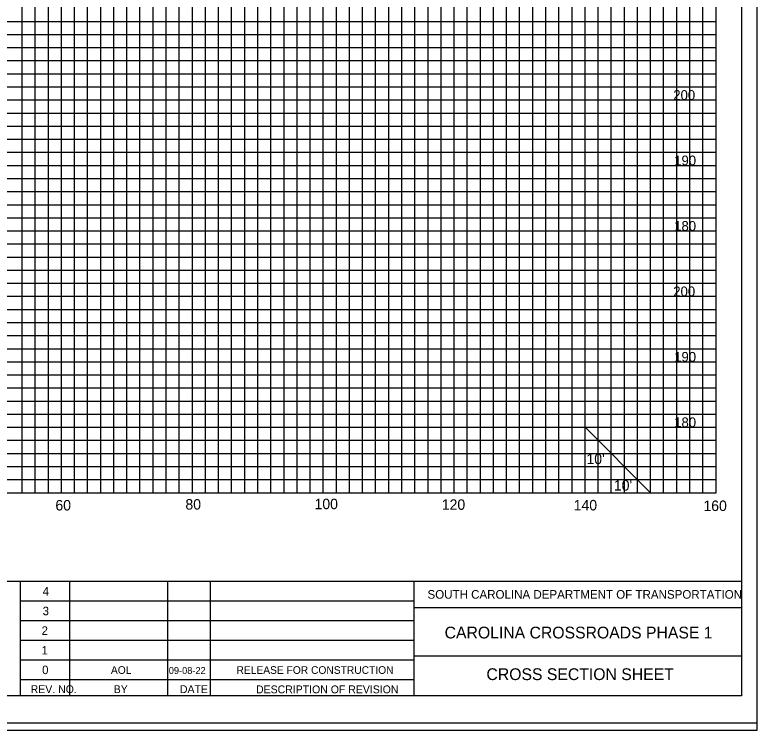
# Model space of a CAD drawing. Extents: x 967 to 1326, y 964 to 2584.
# Drawn here: x 1212.9 to 1326.3, y 2083.7 to 2193 of the extents above; entities that cross this region are included whole.
import ezdxf

# ---------------------------------------------------------------- set-up
doc = ezdxf.new("R2010")
doc.units = 0
for name, color, linetype in [('Default', 7, 'Continuous'), ('RD_GPK_XS_Cell', 7, 'Continuous'), ('RD_SHT_Misc1', 7, 'Continuous'), ('RD_XS_ExGround', 7, 'Continuous'), ('RD_XS_ExPaveRet', 7, 'Continuous'), ('RD_XS_Misc_Line', 7, 'Continuous'), ('RD_XS_TX_Elev_EX', 7, 'Continuous')]:
    doc.layers.add(name, color=color, linetype=linetype)

msp = doc.modelspace()

# ---------------------------------------------------------------- linework, layer by layer
at = {"layer": 'RD_GPK_XS_Cell'}
for p, q in [((1220, 2120), (1220, 2290)), ((1230, 2120), (1230, 2290)), ((1240, 2120), (1240, 2290)), ((1250, 2120), (1250, 2290)), ((1260, 2120), (1260, 2290)), ((1270, 2120), (1270, 2290)), ((1280, 2120), (1280, 2290)), ((1290, 2120), (1290, 2290)), ((1300, 2120), (1300, 2290)), ((1310, 2120), (1310, 2290)), ((1320, 2120), (1320, 2290)), ((1000, 2190), (1320, 2190)), ((1000, 2180), (1320, 2180)), ((1000, 2170), (1320, 2170)), ((1000, 2160), (1320, 2160)), ((1000, 2150), (1320, 2150)), ((1000, 2140), (1320, 2140)), ((1000, 2130), (1320, 2130)), ((1000, 2120), (1320, 2120))]:
    msp.add_line(p, q, dxfattribs=at)
at = {"layer": 'RD_XS_ExGround'}
for p, q in [((1214, 2120), (1214, 2290)), ((1216, 2120), (1216, 2290)), ((1218, 2120), (1218, 2290)), ((1222, 2120), (1222, 2290)), ((1224, 2120), (1224, 2290)), ((1226, 2120), (1226, 2290)), ((1228, 2120), (1228, 2290)), ((1232, 2120), (1232, 2290)), ((1234, 2120), (1234, 2290)), ((1236, 2120), (1236, 2290)), ((1238, 2120), (1238, 2290)), ((1242, 2120), (1242, 2290)), ((1244, 2120), (1244, 2290)), ((1246, 2120), (1246, 2290)), ((1248, 2120), (1248, 2290)), ((1252, 2120), (1252, 2290)), ((1254, 2120), (1254, 2290)), ((1256, 2120), (1256, 2290)), ((1258, 2120), (1258, 2290)), ((1262, 2120), (1262, 2290)), ((1264, 2120), (1264, 2290)), ((1266, 2120), (1266, 2290)), ((1268, 2120), (1268, 2290)), ((1272, 2120), (1272, 2290)), ((1274, 2120), (1274, 2290)), ((1276, 2120), (1276, 2290)), ((1278, 2120), (1278, 2290)), ((1282, 2120), (1282, 2290)), ((1284, 2120), (1284, 2290)), ((1286, 2120), (1286, 2290)), ((1288, 2120), (1288, 2290)), ((1292, 2120), (1292, 2290)), ((1294, 2120), (1294, 2290)), ((1296, 2120), (1296, 2290)), ((1298, 2120), (1298, 2290)), ((1302, 2120), (1302, 2290)), ((1304, 2120), (1304, 2290)), ((1306, 2120), (1306, 2290)), ((1308, 2120), (1308, 2290)), ((1312, 2120), (1312, 2290)), ((1314, 2120), (1314, 2290)), ((1316, 2120), (1316, 2290)), ((1318, 2120), (1318, 2290)), ((1000, 2192), (1320, 2192)), ((1000, 2188), (1320, 2188)), ((1000, 2186), (1320, 2186)), ((1000, 2184), (1320, 2184)), ((1000, 2182), (1320, 2182)), ((1000, 2178), (1320, 2178)), ((1000, 2176), (1320, 2176)), ((1000, 2174), (1320, 2174)), ((1000, 2172), (1320, 2172)), ((1000, 2168), (1320, 2168)), ((1000, 2166), (1320, 2166)), ((1000, 2164), (1320, 2164)), ((1000, 2162), (1320, 2162)), ((1000, 2158), (1320, 2158)), ((1000, 2156), (1320, 2156)), ((1000, 2154), (1320, 2154)), ((1000, 2152), (1320, 2152)), ((1000, 2148), (1320, 2148)), ((1000, 2146), (1320, 2146)), ((1000, 2144), (1320, 2144)), ((1000, 2142), (1320, 2142)), ((1000, 2138), (1320, 2138)), ((1000, 2136), (1320, 2136)), ((1000, 2134), (1320, 2134)), ((1000, 2132), (1320, 2132)), ((1000, 2128), (1320, 2128)), ((1000, 2126), (1320, 2126)), ((1000, 2124), (1320, 2124)), ((1000, 2122), (1320, 2122))]:
    msp.add_line(p, q, dxfattribs=at)
at = {"layer": 'RD_XS_ExPaveRet'}
for points in [[(967.41, 2083.72), (1326.28, 2083.72), (1326.28, 2303.72), (967.41, 2303.72)], [(988.52, 2084.84), (1326.28, 2084.84), (1326.28, 2302.6), (988.52, 2302.6)]]:
    msp.add_lwpolyline(points, close=True, dxfattribs=at)
at = {"layer": 'RD_XS_Misc_Line'}
msp.add_line((1300, 2130), (1310, 2120), dxfattribs=at)
at = {"layer": 'RD_XS_TX_Elev_EX'}
for p, q in [((1323.89, 2298.46), (1323.89, 2088.98)), ((996.11, 2106.49), (1323.89, 2106.49)), ((1213.76, 2088.94), (1213.76, 2106.49)), ((1221.26, 2088.95), (1221.26, 2106.48)), ((1236.26, 2088.95), (1236.26, 2106.48)), ((1242.76, 2088.95), (1242.76, 2106.48)), ((1273.88, 2088.98), (1273.88, 2106.49)), ((1213.76, 2103.48), (1273.88, 2103.48)), ((1323.93, 2102.43), (1273.88, 2102.43)), ((1213.76, 2100.48), (1273.88, 2100.48)), ((1213.76, 2097.48), (1273.88, 2097.48)), ((1323.89, 2095.04), (1273.88, 2095.04)), ((1213.76, 2094.48), (1273.88, 2094.48)), ((1213.76, 2091.48), (1273.88, 2091.48)), ((1323.89, 2088.98), (996.11, 2088.98))]:
    msp.add_line(p, q, dxfattribs=at)

# ---------------------------------------------------------------- texts
at = {"layer": 'Default'}
for s, p in [('200', (1313.47, 2180)), ('190', (1313.61, 2170)), ('180', (1313.61, 2160)), ('200', (1313.47, 2150)), ('190', (1313.61, 2140)), ('180', (1313.61, 2130))]:
    msp.add_text(s, height=1.5, dxfattribs=at).set_placement(p)
at = {"layer": 'RD_SHT_Misc1'}
for s, height, p in [('AOL', 1.17, (1227.56, 2092.32)), ('RELEASE FOR CONSTRUCTION', 1.17, (1246.74, 2092.32)), ('09-08-22', 1.053, (1236.4, 2092.31))]:
    msp.add_text(s, height=height, dxfattribs=at).set_placement(p)
at = {"layer": 'RD_XS_Misc_Line'}
for s, height, p in [("10'", 1.6, (1300.21, 2124.36)), ("10'", 1.6, (1304.4, 2120.32)), ('60', 1.6, (1219.08, 2117.28)), ('80', 1.6, (1238.94, 2117.42)), ('100', 1.6, (1258.67, 2117.48)), ('120', 1.6, (1278.11, 2117.38)), ('140', 1.6, (1298.26, 2117.29)), ('160', 1.6, (1318.08, 2117.2)), ('4', 1.3, (1217.13, 2104.28)), ('SOUTH CAROLINA DEPARTMENT OF TRANSPORTATION', 1.32, (1275.92, 2103.8)), ('3', 1.3, (1217.13, 2101.28)), ('2', 1.3, (1216.97, 2098.28)), ('1', 1.3, (1216.97, 2095.28)), ('0', 1.3, (1217.05, 2092.28)), ('REV. NO.', 1.2, (1215.3, 2089.38)), ('BY', 1.2, (1227.99, 2089.38)), ('DATE', 1.2, (1238.1, 2089.38)), ('DESCRIPTION OF REVISION', 1.2, (1249.73, 2089.35))]:
    msp.add_text(s, height=height, dxfattribs=at).set_placement(p)
for s, p in [('CAROLINA CROSSROADS PHASE 1', (1278.54, 2097.73)), ('CROSS SECTION SHEET', (1284.93, 2091.37))]:
    msp.add_text(s, height=1.8, rotation=0, dxfattribs=at).set_placement(p)

doc.saveas('drawing.dxf')
